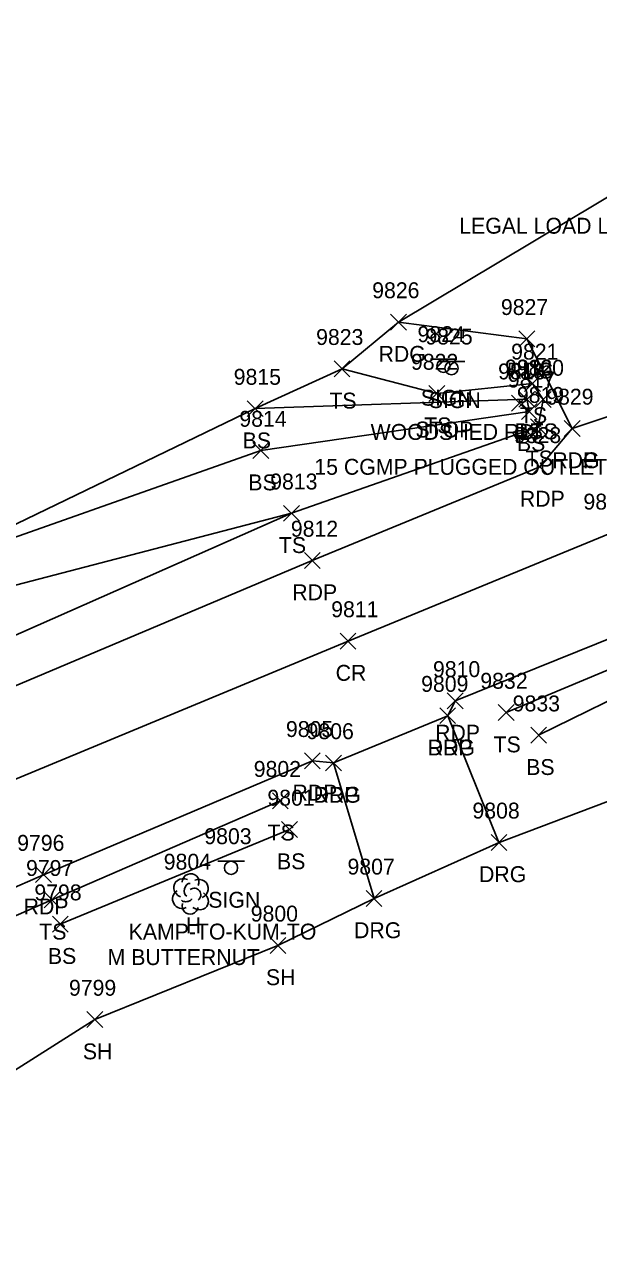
# Model space of a CAD drawing. Extents: x 1651685 to 1653558, y 889533 to 891085.
# Drawn here: x 1651999.4 to 1652071.5, y 889700.1 to 889855.7 of the extents above; entities that cross this region are included whole.
import ezdxf

# ---------------------------------------------------------------- set-up
doc = ezdxf.new("R2010")
doc.units = 0
for name, color, linetype in [('D_A', 7, 'Continuous'), ('D_C', 7, 'Continuous'), ('D_I', 7, 'Continuous'), ('D_TIC', 7, 'Continuous'), ('L_A', 7, 'Continuous'), ('L_C', 7, 'Continuous'), ('L_I', 7, 'Continuous'), ('L_TIC', 7, 'Continuous'), ('LELB', 7, 'Continuous'), ('LSOGP', 7, 'Continuous'), ('LTD', 7, 'Continuous'), ('P_A', 7, 'Continuous'), ('P_I', 7, 'Continuous'), ('P_TIC', 7, 'Continuous'), ('PET', 7, 'Continuous'), ('PEU', 7, 'Continuous'), ('PRC', 7, 'Continuous'), ('R_A', 7, 'Continuous'), ('R_I', 7, 'Continuous'), ('R_TIC', 7, 'Continuous'), ('RDG', 7, 'Continuous'), ('S_A', 7, 'Continuous'), ('S_C', 7, 'Continuous'), ('S_I', 7, 'Continuous'), ('SSGN', 7, 'Continuous')]:
    doc.layers.add(name, color=color, linetype=linetype)

msp = doc.modelspace()

# ---------------------------------------------------------------- linework, layer by layer
at = {"layer": 'D_TIC'}
for points in [[(1652060.63, 889807.07), (1652062.63, 889809.07)], [(1652062.63, 889807.07), (1652060.63, 889809.07)]]:
    msp.add_lwpolyline(points, dxfattribs=at)
at = {"layer": 'L_TIC'}
for points in [[(1652038.29, 889811.4), (1652040.29, 889813.4)], [(1652040.29, 889811.4), (1652038.29, 889813.4)], [(1652062.28, 889809.56), (1652064.28, 889811.56)], [(1652064.28, 889809.56), (1652062.28, 889811.56)], [(1652050.23, 889808.28), (1652052.23, 889810.28)], [(1652052.23, 889808.28), (1652050.23, 889810.28)], [(1652061.55, 889807.56), (1652063.55, 889809.56)], [(1652063.55, 889807.56), (1652061.55, 889809.56)], [(1652063.62, 889807.53), (1652065.62, 889809.53)], [(1652065.62, 889807.53), (1652063.62, 889809.53)], [(1652027.35, 889806.39), (1652029.35, 889808.39)], [(1652029.35, 889806.39), (1652027.35, 889808.39)], [(1652061.87, 889806.04), (1652063.87, 889808.04)], [(1652063.87, 889806.04), (1652061.87, 889808.04)], [(1652061.87, 889806.04), (1652063.87, 889808.04)], [(1652063.87, 889806.04), (1652061.87, 889808.04)], [(1652063, 889804.11), (1652065, 889806.11)], [(1652065, 889804.11), (1652063, 889806.11)], [(1652028.06, 889801.11), (1652030.06, 889803.11)], [(1652030.06, 889801.11), (1652028.06, 889803.11)], [(1652031.94, 889793.22), (1652033.94, 889795.22)], [(1652033.94, 889793.22), (1652031.94, 889795.22)], [(1652031.94, 889793.22), (1652033.94, 889795.22)], [(1652033.94, 889793.22), (1652031.94, 889795.22)], [(1652058.96, 889768.15), (1652060.96, 889770.15)], [(1652060.96, 889768.15), (1652058.96, 889770.15)], [(1652063.04, 889765.3), (1652065.04, 889767.3)], [(1652065.04, 889765.3), (1652063.04, 889767.3)], [(1652030.52, 889757.06), (1652032.52, 889759.06)], [(1652032.52, 889757.06), (1652030.52, 889759.06)], [(1652031.67, 889753.44), (1652033.67, 889755.44)], [(1652033.67, 889753.44), (1652031.67, 889755.44)], [(1652001.78, 889744.6), (1652003.78, 889746.6)], [(1652003.78, 889744.6), (1652001.78, 889746.6)], [(1652002.83, 889741.53), (1652004.83, 889743.53)], [(1652004.83, 889741.53), (1652002.83, 889743.53)], [(1652030.23, 889738.86), (1652032.23, 889740.86)], [(1652032.23, 889738.86), (1652030.23, 889740.86)], [(1652007.19, 889729.53), (1652009.19, 889731.53)], [(1652009.19, 889729.53), (1652007.19, 889731.53)]]:
    msp.add_lwpolyline(points, dxfattribs=at)
at = {"layer": 'LELB'}
for points in [[(1652059.96, 889769.15), (1652077.1, 889776.34), (1652118.69, 889793.55), (1652148.83, 889805.14), (1652195.57, 889824.7), (1652235.22, 889839.02), (1652273.17, 889851.71), (1652312.19, 889868.5), (1652346.46, 889887.35), (1652384.44, 889904.89), (1652418.63, 889927.64), (1652449.26, 889948.79), (1652484.18, 889973.18), (1652505.9, 889994.66), (1652536.9, 890025.51), (1652566.28, 890055.69), (1652594.63, 890083.58), (1652622.18, 890122.04), (1652650.06, 890154.47), (1652669.87, 890181.83), (1652676.09, 890189.41), (1652687.77, 890202.23), (1652700.09, 890224.17)], [(1652064.04, 889766.3), (1652078.59, 889773.44), (1652119.73, 889790.45), (1652150.48, 889803.01), (1652196.54, 889821.75), (1652237.97, 889833.58), (1652274.81, 889846.26), (1652318.57, 889855.03)], [(1651783.6, 889675.23), (1651805.26, 889676.92), (1651818.09, 889682.86), (1651843.19, 889699.23), (1651855.35, 889704.9), (1651888.23, 889726.95), (1651920.63, 889744.86), (1651960.2, 889763.86), (1651990.86, 889775.67), (1652032.94, 889794.22), (1652064, 889805.11), (1652064.62, 889808.53), (1652063.28, 889810.56), (1652051.23, 889809.28), (1652039.29, 889812.4)], [(1652028.35, 889807.39), (1652062.55, 889808.56), (1652062.87, 889807.04)], [(1651845.19, 889705.05), (1651852.98, 889708.46), (1651886.2, 889730.12), (1651918.71, 889747.83), (1651956.73, 889770.8), (1651985.79, 889786.86), (1652029.06, 889802.11), (1652062.87, 889807.04)], [(1651987.72, 889782.44), (1652032.94, 889794.22)], [(1651914.13, 889704.26), (1651933.92, 889714.66), (1651972.97, 889732.49), (1652002.78, 889745.6), (1652031.52, 889758.06)], [(1652003.83, 889742.53), (1652032.67, 889754.44)]]:
    msp.add_lwpolyline(points, dxfattribs=at)
at = {"layer": 'LSOGP'}
for points in [[(1652344.51, 889962.98), (1652311.88, 889950.06), (1652319.83, 889936.28), (1652297.31, 889917.06), (1652293.22, 889915.65), (1652288.54, 889913.18), (1652275.12, 889907.88), (1652271.2, 889906.55), (1652269.1, 889906.41), (1652254.49, 889898.49), (1652214.38, 889884.21), (1652189.89, 889872.39), (1652177.7, 889863.92), (1652130.38, 889845.03), (1652128.61, 889848.08), (1652100.57, 889839.31), (1652088.78, 889837.26), (1652079.97, 889838.39), (1652075.93, 889835.91), (1652046.4, 889818.27), (1652039.29, 889812.4), (1652028.35, 889807.39), (1651985.79, 889786.86)], [(1651980.89, 889713.26), (1652008.19, 889730.53), (1652031.23, 889739.86), (1652043.32, 889745.77), (1652059.06, 889752.82), (1652082.8, 889761.8), (1652098.21, 889765.57), (1652124.91, 889780.84), (1652162.24, 889787.9), (1652185.04, 889794.86), (1652201.07, 889811.05), (1652242.25, 889825.35), (1652276.97, 889838.55), (1652318.58, 889855.03), (1652374.55, 889845.16)]]:
    msp.add_lwpolyline(points, dxfattribs=at)
at = {"layer": 'LTD'}
msp.add_line((1652020.19, 889746.39), (1652020.19, 889746.39), dxfattribs=at)
msp.add_line((1652020.19, 889746.39), (1652020.19, 889746.39), dxfattribs=at)
msp.add_arc((1652020.24, 889747.83), 1.05, 335.5272, 180.9563, dxfattribs=at)
for centre, major_axis, ratio, start_param, end_param in [((1652019.4, 889747.06), (1.21, -0.51), 0.895232, 1.570796, 4.712389), ((1652019.98, 889746.85), (-0.208, -0.792), 0.645439, 3.141593, 6.283185), ((1652021.23, 889746.98), (-1.14, -0.48), 0.949671, 1.570796, 4.712389), ((1652019.11, 889745.68), (0.58, -1.04), 0.959034, 3.141593, 6.283185), ((1652019.73, 889745.64), (-0.625, -0.083), 0.423636, 0, 3.141593), ((1652020.69, 889746.23), (-0.5, 0.667), 0.989748, 3.141593, 6.283185), ((1652021.19, 889745.56), (-1.09, 0.79), 0.841452, 1.570796, 4.712389), ((1652020.19, 889744.89), (0.26, 1.06), 0.942809, 1.570796, 4.712389)]:
    msp.add_ellipse(centre, major_axis=major_axis, ratio=ratio, start_param=start_param, end_param=end_param, dxfattribs=at)
at = {"layer": 'P_TIC'}
for points in [[(1652045.4, 889817.28), (1652047.4, 889819.28)], [(1652047.4, 889817.28), (1652045.4, 889819.28)], [(1652061.55, 889815.17), (1652063.55, 889817.17)], [(1652063.55, 889815.17), (1652061.55, 889817.17)], [(1652067.27, 889803.89), (1652069.27, 889805.89)], [(1652069.27, 889803.89), (1652067.27, 889805.89)], [(1652067.27, 889803.89), (1652069.27, 889805.89)], [(1652069.27, 889803.89), (1652067.27, 889805.89)], [(1652063.19, 889799.06), (1652065.19, 889801.06)], [(1652065.19, 889799.06), (1652063.19, 889801.06)], [(1652034.55, 889787.28), (1652036.55, 889789.28)], [(1652036.55, 889787.28), (1652034.55, 889789.28)], [(1652039.05, 889777.15), (1652041.05, 889779.15)], [(1652041.05, 889777.15), (1652039.05, 889779.15)], [(1652052.52, 889769.62), (1652054.52, 889771.62)], [(1652054.52, 889769.62), (1652052.52, 889771.62)], [(1652051.59, 889767.76), (1652053.59, 889769.76)], [(1652053.59, 889767.76), (1652051.59, 889769.76)], [(1652034.56, 889762.08), (1652036.56, 889764.08)], [(1652036.56, 889762.08), (1652034.56, 889764.08)], [(1652037.22, 889761.81), (1652039.22, 889763.81)], [(1652039.22, 889761.81), (1652037.22, 889763.81)], [(1652000.72, 889747.76), (1652002.72, 889749.76)], [(1652002.72, 889747.76), (1652000.72, 889749.76)]]:
    msp.add_lwpolyline(points, dxfattribs=at)
at = {"layer": 'PET'}
for points in [[(1651993.09, 889770.39), (1652035.55, 889788.28), (1652064.19, 889800.06), (1652068.27, 889804.89), (1652108.23, 889818.22), (1652137.76, 889829.36), (1652185.37, 889848.31), (1652223.8, 889864.06), (1652262.57, 889880.14), (1652279.91, 889887.76), (1652294.79, 889894.11), (1652333.65, 889912.67), (1652369.12, 889931.53)], [(1651722.05, 889556.64), (1651743.79, 889579.05), (1651773.7, 889607.56), (1651801.99, 889632.45), (1651834.2, 889657.45), (1651868.37, 889681.24), (1651890.21, 889694.54), (1651910.42, 889705.67), (1651932.43, 889717.43), (1651971.73, 889735.64), (1652001.72, 889748.76), (1652035.56, 889763.08), (1652038.22, 889762.81), (1652052.59, 889768.76), (1652053.52, 889770.62), (1652076.54, 889779.88), (1652117.63, 889796.48), (1652147.54, 889808.21), (1652195.16, 889826.81), (1652233.48, 889842.54), (1652271.73, 889857.62), (1652310.07, 889873.86), (1652345.02, 889890.88)]]:
    msp.add_lwpolyline(points, dxfattribs=at)
at = {"layer": 'PEU'}
msp.add_lwpolyline([(1652046.4, 889818.28), (1652062.55, 889816.17), (1652068.27, 889804.89)], dxfattribs=at)
at = {"layer": 'PRC'}
msp.add_lwpolyline([(1651712.82, 889564.71), (1651734.46, 889586.87), (1651766.27, 889617.28), (1651793.27, 889641.25), (1651826.92, 889667.91), (1651862.27, 889692.04), (1651896.77, 889712.72), (1651926.87, 889728.69), (1651966.67, 889747.09), (1651996.7, 889760.13), (1652040.05, 889778.15), (1652073.02, 889791.69), (1652113.32, 889807.56), (1652142.44, 889819.25), (1652190.37, 889838.24), (1652228.92, 889853.82), (1652266.92, 889869.48), (1652304.43, 889885.84), (1652339.13, 889902.36), (1652374.76, 889921.45)], dxfattribs=at)
at = {"layer": 'R_TIC'}
for points in [[(1652051.59, 889767.76), (1652053.59, 889769.76)], [(1652053.59, 889767.76), (1652051.59, 889769.76)], [(1652037.22, 889761.81), (1652039.22, 889763.81)], [(1652039.22, 889761.81), (1652037.22, 889763.81)], [(1652058.05, 889751.82), (1652060.05, 889753.82)], [(1652060.05, 889751.82), (1652058.05, 889753.82)], [(1652042.32, 889744.77), (1652044.32, 889746.77)], [(1652044.32, 889744.77), (1652042.32, 889746.77)]]:
    msp.add_lwpolyline(points, dxfattribs=at)
at = {"layer": 'RDG'}
for points in [[(1652059.05, 889752.82), (1652052.59, 889768.76)], [(1652038.22, 889762.81), (1652043.32, 889745.77)]]:
    msp.add_lwpolyline(points, dxfattribs=at)
at = {"layer": 'SSGN'}
for p, q in [((1652050.42, 889813.62), (1652053.76, 889813.62)), ((1652051.43, 889813.31), (1652054.76, 889813.31)), ((1652052.07, 889812.78), (1652052.07, 889812.78)), ((1652053.07, 889812.48), (1652053.07, 889812.48)), ((1652023.67, 889750.46), (1652027.01, 889750.46)), ((1652025.32, 889749.62), (1652025.32, 889749.62))]:
    msp.add_line(p, q, dxfattribs=at)
for centre in [(1652052.07, 889812.78), (1652053.07, 889812.48), (1652025.32, 889749.62)]:
    msp.add_circle(centre, 0.833, dxfattribs=at)

# ---------------------------------------------------------------- texts
at = {"layer": 'D_A'}
msp.add_text('P', height=2, dxfattribs=at).set_placement((1652061.01, 889803.07))
at = {"layer": 'D_C'}
msp.add_text('15 CGMP PLUGGED OUTLET BURIED', height=2, dxfattribs=at).set_placement((1652035.81, 889799.07))
at = {"layer": 'D_I'}
msp.add_text('9818', height=2, dxfattribs=at).set_placement((1652058.94, 889811.07))
at = {"layer": 'L_A'}
for s, p in [('TS', (1652037.7, 889807.4)), ('TS', (1652061.69, 889805.56)), ('TS', (1652049.64, 889804.28)), ('BS', (1652061, 889803.56)), ('TS', (1652063.03, 889803.53)), ('BS', (1652026.79, 889802.39)), ('BS', (1652061.31, 889802.04)), ('BS', (1652061.31, 889802.04)), ('TS', (1652062.41, 889800.11)), ('BS', (1652027.5, 889797.11)), ('TS', (1652031.35, 889789.22)), ('TS', (1652031.35, 889789.22)), ('TS', (1652058.37, 889764.15)), ('BS', (1652062.48, 889761.3)), ('TS', (1652029.93, 889753.06)), ('BS', (1652031.11, 889749.44)), ('TS', (1652001.19, 889740.6)), ('H', (1652019.63, 889741.39)), ('BS', (1652002.27, 889737.53)), ('SH', (1652029.72, 889734.86)), ('SH', (1652006.67, 889725.53))]:
    msp.add_text(s, height=2, dxfattribs=at).set_placement(p)
at = {"layer": 'L_C'}
msp.add_text('M BUTTERNUT', height=2, dxfattribs=at).set_placement((1652009.79, 889737.39))
at = {"layer": 'L_I'}
for s, p in [('9823', (1652036.03, 889815.4)), ('9822', (1652047.97, 889812.28)), ('9821', (1652060.58, 889813.56)), ('9816', (1652059.81, 889811.56)), ('9820', (1652061.28, 889811.53)), ('9815', (1652025.66, 889810.39)), ('9817', (1652060.17, 889810.04)), ('9817', (1652060.17, 889810.04)), ('9819', (1652061.3, 889808.11)), ('9814', (1652026.37, 889805.11)), ('9813', (1652030.25, 889797.22)), ('9813', (1652030.25, 889797.22)), ('9832', (1652056.7, 889772.15)), ('9833', (1652060.78, 889769.3)), ('9802', (1652028.18, 889761.06)), ('9801', (1652029.9, 889757.44)), ('9797', (1651999.52, 889748.6)), ('9804', (1652016.85, 889749.39)), ('9798', (1652000.57, 889745.53)), ('9800', (1652027.8, 889742.86)), ('9799', (1652004.92, 889733.53))]:
    msp.add_text(s, height=2, dxfattribs=at).set_placement(p)
at = {"layer": 'P_A'}
for s, p in [('RDG', (1652043.89, 889813.28)), ('RDG', (1652060.03, 889811.17)), ('RDG', (1652065.76, 889799.89)), ('RDP', (1652065.76, 889799.89)), ('RDP', (1652061.68, 889795.06)), ('RDP', (1652033.03, 889783.28)), ('CR', (1652038.49, 889773.15)), ('RDP', (1652051.01, 889765.62)), ('RDP', (1652050.08, 889763.76)), ('RDP', (1652033.05, 889758.08)), ('RDP', (1652035.71, 889757.81)), ('RDP', (1651999.21, 889743.76))]:
    msp.add_text(s, height=2, dxfattribs=at).set_placement(p)
at = {"layer": 'P_I'}
for s, p in [('9826', (1652043.09, 889821.28)), ('9827', (1652059.29, 889819.17)), ('9829', (1652065, 889807.89)), ('9829', (1652065, 889807.89)), ('9828', (1652060.93, 889803.06)), ('9830', (1652069.68, 889794.69)), ('9812', (1652032.85, 889791.28)), ('9811', (1652037.93, 889781.15)), ('9810', (1652050.74, 889773.62)), ('9809', (1652049.25, 889771.76)), ('9805', (1652032.23, 889766.08)), ('9806', (1652034.83, 889765.81)), ('9796', (1651998.4, 889751.76))]:
    msp.add_text(s, height=2, dxfattribs=at).set_placement(p)
at = {"layer": 'R_A'}
for p in [(1652050.08, 889763.76), (1652035.71, 889757.81), (1652056.54, 889747.82), (1652040.81, 889740.77)]:
    msp.add_text('DRG', height=2, dxfattribs=at).set_placement(p)
at = {"layer": 'R_I'}
for s, p in [('9809', (1652049.25, 889771.76)), ('9806', (1652034.83, 889765.81)), ('9808', (1652055.71, 889755.82)), ('9807', (1652039.98, 889748.77))]:
    msp.add_text(s, height=2, dxfattribs=at).set_placement(p)
at = {"layer": 'S_A'}
for p in [(1652049.21, 889807.76), (1652050.21, 889807.46), (1652022.46, 889744.6)]:
    msp.add_text('SIGN', height=2, dxfattribs=at).set_placement(p)
at = {"layer": 'S_C'}
for s, p in [('LEGAL LOAD LIMIT 24000 POUNDS', (1652054.05, 889829.4)), ('WOODSHED RD', (1652042.89, 889803.46)), ('STOP', (1652048.53, 889803.76)), ('KAMP-TO-KUM-TO', (1652012.44, 889740.6))]:
    msp.add_text(s, height=2, dxfattribs=at).set_placement(p)
at = {"layer": 'S_I'}
for s, p in [('9824', (1652048.79, 889815.76)), ('9825', (1652049.79, 889815.46)), ('9803', (1652021.96, 889752.6))]:
    msp.add_text(s, height=2, dxfattribs=at).set_placement(p)

doc.saveas('drawing.dxf')
